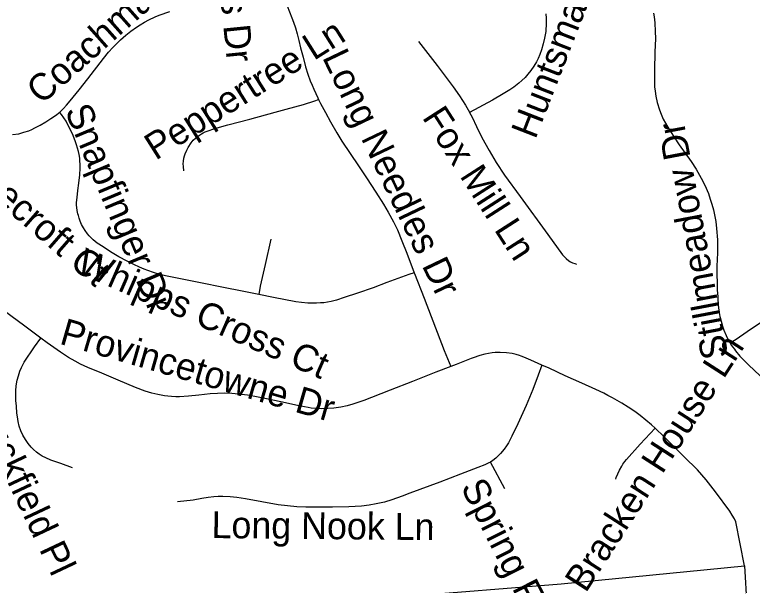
# Model space of a CAD drawing. Extents: x 1383679 to 1536984, y 460658 to 651027.
# Drawn here: x 1459289 to 1461906, y 478901 to 480927 of the extents above; entities that cross this region are included whole.
import ezdxf

# ---------------------------------------------------------------- set-up
doc = ezdxf.new("R2010")
doc.units = 0
doc.layers.add('Exist Road Non-System Type 51', color=7, linetype='Continuous')
doc.layers.add('Exist Road Non-System Type 51 Label', color=7, linetype='Continuous')

msp = doc.modelspace()

# ---------------------------------------------------------------- linework, layer by layer
at = {"layer": 'Exist Road Non-System Type 51'}
msp.add_line((1461028.9, 479243.6), (1460977, 479338), dxfattribs=at)
for points in [[(1460229.7, 481013.5), (1460242.3, 480986.7), (1460255.4, 480958.4), (1460264.8, 480937.2), (1460273, 480915.9), (1460278.8, 480900.2), (1460285.3, 480880.7), (1460291.4, 480858.3), (1460297.3, 480835.3), (1460303.6, 480809.3), (1460312.2, 480775.4), (1460321.4, 480742.1), (1460329.7, 480715.7), (1460337.8, 480692.4), (1460344.2, 480676.4), (1460350.4, 480661.8), (1460364.7, 480631.6), (1460367.5, 480626.1)], [(1459281.6, 480500.8), (1459304.1, 480504.3), (1459322.1, 480509.1), (1459338.7, 480514.5), (1459349.7, 480519.3), (1459360.7, 480524.7), (1459378.9, 480534.1), (1459400.1, 480546.4), (1459417, 480557.6), (1459433.7, 480569.2), (1459448.7, 480581), (1459461.8, 480593.3), (1459472.6, 480605.4), (1459486.5, 480621.5), (1459518.1, 480659.6), (1459548.5, 480698.5), (1459604.1, 480771.6), (1459622, 480793.4), (1459637.6, 480810.6), (1459652.8, 480826), (1459664.8, 480837.2), (1459683.2, 480853.8), (1459701.2, 480868.1), (1459721.5, 480883.1), (1459733.8, 480891.3), (1459749.5, 480900.8), (1459764.6, 480908.7), (1459787.8, 480919.6), (1459801.7, 480925), (1459839.6, 480938.2)], [(1461174.4, 480929.5), (1461175.2, 480914.6), (1461175.4, 480896.7), (1461173.4, 480867), (1461169.4, 480843), (1461164.8, 480823.6), (1461158.5, 480802.4), (1461152.2, 480785), (1461146.1, 480770.9), (1461140.3, 480759.1), (1461131.5, 480744.3), (1461121.1, 480729), (1461110.2, 480715.1), (1461100.1, 480703.9), (1461088.9, 480693), (1461077.8, 480683.2), (1461059.7, 480669.4), (1461045.9, 480659.8), (1461022.7, 480645.2), (1460984, 480623.5), (1460903.4, 480580)], [(1461556.1, 480932.2), (1461558.1, 480918.7), (1461560.2, 480897.7), (1461561.9, 480867.2), (1461562.5, 480841.9), (1461560.6, 480794.2), (1461559.1, 480731.2), (1461559.5, 480683.2), (1461560, 480671.2), (1461561.6, 480655.7), (1461564.5, 480636.9), (1461569.3, 480614.9), (1461576.9, 480589.3), (1461582.5, 480574.1), (1461590.7, 480556.4), (1461606.4, 480527.9), (1461613.9, 480516.1), (1461647.5, 480465.2), (1461689.9, 480405.2), (1461707.4, 480378), (1461725.5, 480346.3), (1461738.2, 480321.1), (1461750.7, 480291.9), (1461757.4, 480272.2), (1461762.7, 480254.1), (1461768.6, 480233.8), (1461773.8, 480210.4), (1461776.9, 480192.1), (1461779.9, 480167.9), (1461782.4, 480127.6), (1461782.4, 480081), (1461781.1, 480033.5), (1461781, 479997.7), (1461781.4, 479980.3), (1461782.1, 479944.7), (1461782.5, 479942.7), (1461785.1, 479896.4), (1461787.7, 479876), (1461791.5, 479855.5), (1461795.5, 479838.2), (1461800.7, 479820.4), (1461805.4, 479806.5), (1461813.2, 479787.6), (1461821.1, 479772.2), (1461827.5, 479761.4)], [(1460721.7, 480831.5), (1460787.7, 480746.3), (1460844.6, 480671), (1460867.2, 480638.5), (1460888.3, 480605.9), (1460903, 480580.7), (1460903.4, 480580)], [(1459888.8, 480371.8), (1459887.7, 480387.3), (1459887.3, 480397.3), (1459887.7, 480406.6), (1459889.7, 480417.1), (1459892.1, 480425.3), (1459894.5, 480432.2), (1459900, 480445.9), (1459904.5, 480455), (1459915.1, 480472), (1459922.7, 480481.1), (1459931.2, 480488.9), (1459937.1, 480493.6), (1459944.9, 480499.4), (1459952.1, 480503.8), (1459958.1, 480506.9), (1459965.5, 480510.5), (1459972.6, 480513.4), (1459999.2, 480522.3), (1460044.9, 480535.3), (1460123.4, 480556.3), (1460213.4, 480580.1), (1460252.9, 480590.8), (1460313.7, 480607.9), (1460354.1, 480620.7), (1460367.5, 480626.1)], [(1460367.5, 480626.1), (1460374.7, 480611.8), (1460391.9, 480579.6), (1460409.2, 480546.9), (1460432.4, 480506.9), (1460450.5, 480477.3), (1460479.4, 480434.2), (1460509.2, 480389.9), (1460537.7, 480347.1), (1460570.8, 480296.8), (1460597.7, 480254.2), (1460614.4, 480225.7), (1460633.5, 480191.1), (1460647, 480162.9), (1460663, 480123.8), (1460680.4, 480080), (1460706.6, 480010.7)], [(1460155.8, 479933), (1460102.3, 479943.3), (1460024.1, 479959.3), (1459954.2, 479973.3), (1459888.7, 479986.1), (1459836.4, 479996.7), (1459808.2, 480003.3), (1459781.6, 480011.4), (1459761.9, 480018.1), (1459748.2, 480023.5), (1459731.8, 480030.1), (1459711.4, 480039.4), (1459688.1, 480051), (1459658.7, 480066.7), (1459629, 480084.4), (1459603.3, 480101.9), (1459582.3, 480115.8), (1459567.8, 480127.1), (1459560.2, 480134.2), (1459553.2, 480141.9), (1459546.9, 480149.1), (1459538.8, 480160.7), (1459532.8, 480170.5), (1459526.2, 480182.3), (1459521.2, 480193.9), (1459517.9, 480203.8), (1459515, 480214.3), (1459513.6, 480219.6), (1459511.2, 480231.7), (1459509.7, 480242), (1459509, 480250.9), (1459508.9, 480259.4), (1459510.2, 480277.3), (1459513.4, 480302.2), (1459516.8, 480328), (1459519.8, 480357.9), (1459521, 480381.7), (1459521.1, 480395.8), (1459520.8, 480407.1), (1459520, 480416.7), (1459518.9, 480424.7), (1459518, 480430), (1459515.8, 480440.6), (1459512.4, 480452.7), (1459508.8, 480464.8), (1459505.2, 480475.2), (1459496.3, 480498.4), (1459490.8, 480510.4), (1459485, 480521.8), (1459471.5, 480548.2), (1459463.7, 480561), (1459455.2, 480572), (1459449, 480579.4)], [(1460903.4, 480580), (1460912.5, 480562.9), (1460927.3, 480530.1), (1460947.1, 480491.2), (1460972.5, 480444.2), (1460997, 480402), (1461027, 480356.6), (1461083, 480281.1), (1461180.8, 480146.1), (1461233.2, 480074.5), (1461245.6, 480061.1), (1461255.6, 480052.6), (1461261.1, 480049.2), (1461268.7, 480045.6), (1461276.3, 480042.9), (1461283, 480041)], [(1460198, 480129.3), (1460177.9, 480039.9), (1460160.7, 479962.8), (1460155.8, 479933)], [(1459382, 479778), (1459325.4, 479821.1), (1459225, 479894.4), (1459149.1, 479949.9), (1459128.6, 479963.5), (1459116.5, 479971.1), (1459103.9, 479978.2), (1459088.3, 479986), (1459070.5, 479993.7), (1459055, 479999.1), (1459044, 480002), (1459032.9, 480004.5), (1459018.2, 480006.3), (1458963.4, 480008.3), (1458920.9, 480010.2)], [(1460706.6, 480010.7), (1460687.3, 480003.7), (1460610.2, 479976.3), (1460560.6, 479957.1), (1460505, 479937.7), (1460457.9, 479922), (1460431.3, 479913.4), (1460411.6, 479908.3), (1460398.6, 479905.8), (1460386.1, 479904), (1460374.8, 479903.1), (1460360.2, 479902.3), (1460346.6, 479902.2), (1460329.2, 479903), (1460306.3, 479905.2), (1460287.2, 479907.7), (1460207, 479923.1), (1460155.8, 479933)], [(1460706.6, 480010.7), (1460707.6, 480007.9), (1460741.7, 479919.6), (1460813.6, 479734.4), (1460836.7, 479677.2)], [(1461827.5, 479761.4), (1461849.2, 479775.1), (1461888.3, 479801.3), (1461935.1, 479833.2), (1462039, 479901.9), (1462075, 479924.3), (1462139.7, 479960.2), (1462167.1, 479972.5)], [(1459493.8, 479318.2), (1459453, 479332.8), (1459431.3, 479340.6), (1459417.8, 479345.4), (1459400.1, 479353.2), (1459387, 479359.6), (1459375.5, 479366.3), (1459366.1, 479373.8), (1459355.9, 479382.9), (1459347.8, 479391), (1459337.1, 479404.4), (1459327.7, 479418.3), (1459318.1, 479434.1), (1459311.1, 479448.9), (1459305.5, 479466), (1459301.7, 479482.7), (1459299, 479499), (1459297.1, 479512.2), (1459295.3, 479536.8), (1459293.6, 479556.9), (1459292.8, 479575.4), (1459292.8, 479591), (1459294.8, 479608.3), (1459298.2, 479628.9), (1459302.3, 479644.9), (1459307, 479660.4), (1459312.8, 479673.9), (1459323.3, 479692.6), (1459359.2, 479747.2), (1459382, 479778)], [(1460836.7, 479677.2), (1460784, 479656.9), (1460701, 479624.3), (1460621.7, 479594), (1460555.5, 479567), (1460527.7, 479556.5), (1460502.8, 479547.9), (1460489.4, 479543.9), (1460469.1, 479537.9), (1460446.3, 479532.9), (1460421.6, 479529), (1460399.7, 479527.8), (1460376.7, 479527.4), (1460362.3, 479528.1), (1460340.9, 479530), (1460330.8, 479531.5), (1460317.8, 479533.9), (1460286.5, 479540.4), (1460250, 479548.5), (1460188.5, 479561.2), (1460141.5, 479571.1), (1460115.2, 479575.8), (1460083, 479579.7), (1460059.8, 479581.3), (1460032.6, 479582.3), (1460009.2, 479581.8), (1459982.4, 479579.9), (1459942, 479575.9), (1459906, 479572.6), (1459873.9, 479570.2), (1459861.3, 479570.3), (1459845.6, 479570.9), (1459832.8, 479571.7), (1459820.1, 479573.2), (1459797.5, 479577.5), (1459776.1, 479582.5), (1459751.6, 479590), (1459718, 479602.9), (1459655.7, 479628.5), (1459598.4, 479653.6), (1459548.7, 479674.2), (1459522.5, 479686.3), (1459504.2, 479695.9), (1459480.1, 479709.9), (1459451.1, 479728.2), (1459404.2, 479761.1), (1459382, 479778)], [(1461827.5, 479761.4), (1461831.9, 479753.8), (1461843.1, 479738.7), (1461847.4, 479732.7), (1461862.5, 479714.5), (1461893.5, 479683.3), (1461954.8, 479625), (1462016.5, 479568.9), (1462047.3, 479540.6), (1462075, 479512.2), (1462085.1, 479501.8), (1462121, 479457.3), (1462138.9, 479430.8), (1462151.3, 479410.2), (1462162.4, 479386.9), (1462176.2, 479361.1)], [(1461160.1, 479682.4), (1461121, 479700), (1461095.5, 479711), (1461086.6, 479714.6), (1461080.8, 479716.8), (1461068.6, 479720.6), (1461058.9, 479722.9), (1461054.2, 479723.6), (1461033.8, 479726.3), (1461011.8, 479727.5), (1460994.4, 479727.1), (1460983.7, 479726.1), (1460969.9, 479724), (1460957.3, 479721.4), (1460940.1, 479716.7), (1460916.2, 479708.6), (1460908.9, 479705.7), (1460855.4, 479684.5), (1460836.7, 479677.2)], [(1461160.1, 479682.4), (1461147.2, 479646.5), (1461127.7, 479596.4), (1461103.9, 479539.3), (1461074.2, 479474), (1461053.1, 479430), (1461040.8, 479406.3), (1461034.4, 479395.8), (1461025.9, 479384.2), (1461013, 479369.1), (1461003.8, 479359.1), (1460996, 479351.7), (1460986, 479344), (1460977.3, 479338.2), (1460977, 479338)], [(1461561.3, 479458.2), (1461548.5, 479470.5), (1461508.2, 479503.4), (1461493.8, 479514.1), (1461478.5, 479525), (1461466.5, 479533), (1461443.6, 479547.8), (1461427.1, 479557.2), (1461410.3, 479566.5), (1461394, 479575), (1461379.5, 479582.4), (1461350.7, 479595.7), (1461301.3, 479617.8), (1461242.6, 479644.8), (1461185.2, 479671.1), (1461160.1, 479682.4)], [(1461421.9, 479277), (1461423.9, 479283.5), (1461429.2, 479296.7), (1461434.7, 479308.9), (1461443.2, 479324.1), (1461447.4, 479331), (1461454, 479339.8), (1461460.3, 479347.1), (1461509, 479401.5), (1461561.3, 479458.2)], [(1461879.1, 478969.5), (1461847.8, 479125.5), (1461843.2, 479136), (1461835.3, 479149.6), (1461826.3, 479163.8), (1461775.5, 479231.9), (1461742.2, 479275.2), (1461712.5, 479310), (1461664.7, 479357.2), (1461593.4, 479427.4), (1461561.3, 479458.2)], [(1460977, 479338), (1460968.9, 479333.7), (1460957.6, 479328.7), (1460932.2, 479318.4), (1460870.5, 479295), (1460797.4, 479266.3), (1460691, 479227.3), (1460664, 479216.9), (1460627, 479203.6), (1460601, 479196.3), (1460572.1, 479189.6), (1460546.5, 479185.5), (1460519.2, 479182), (1460474.7, 479179), (1460417.2, 479178.2), (1460364.8, 479178), (1460322.3, 479178.2), (1460289.7, 479179.7), (1460257.1, 479182.5), (1460224, 479186.6), (1460165.7, 479196.5), (1460107.6, 479207.9), (1460077.2, 479212.6), (1460054, 479214.8), (1460027.5, 479215.9), (1460010.8, 479215.8), (1459996, 479214.7), (1459975.7, 479212.1), (1459952.7, 479208.2), (1459922.4, 479203.1), (1459867, 479196.6)], [(1460668.2, 478861.1), (1461227.7, 478906.3), (1461673.8, 478949.8), (1461879.1, 478969.5)], [(1461879.1, 478969.5), (1461887, 478827.3), (1461871.2, 478609.9), (1461831.7, 478380.8), (1461792.3, 478246.4)]]:
    msp.add_lwpolyline(points, dxfattribs=at)

# ---------------------------------------------------------------- texts
at = {"layer": 'Exist Road Non-System Type 51 Label'}
for s, rotation, p in [('Colony Woods Dr', 275.7732, (1459942.4, 481745.1)), ('Huntsmaster Dr', 68.7417, (1461136.6, 480481.5)), ('Coachman Cr', 41.5974, (1459384.2, 480605)), ('Peppertree Ln', 32.2695, (1459789.2, 480407.8)), ('Long Needles Dr', 295.5512, (1460379.2, 480775.7)), ('Snapfinger Dr', 292.7562, (1459465.9, 480586)), ('Fox Mill Ln', 302.7102, (1460732.9, 480562)), ('Stillmeadow Dr', 100.7244, (1461821.8, 479712.9)), ('Horsecroft Ct', 318.9759, (1459010.7, 480448.2)), ('Whipps Cross Ct', 336.3934, (1459503, 480013.7)), ('Provincetowne Dr', 343.8717, (1459444.6, 479758.9)), ('Bracken House Ln', 57.2301, (1461315.5, 478870.7)), ('Buckfield Pl', 295.2508, (1459139.7, 479527.3)), ('Spring Fancy Ln', 296.8958, (1460870.3, 479249.6)), ('Long Nook Ln', 359.4604, (1459987.3, 479068.3))]:
    msp.add_text(s, height=95, rotation=rotation, dxfattribs=at).set_placement(p)

doc.saveas('drawing.dxf')
